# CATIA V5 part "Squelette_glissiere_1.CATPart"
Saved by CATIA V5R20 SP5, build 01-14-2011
Part number: Squelette_glissiere
Publications: "Longueur_int_coulisseau_1", "Longueur_ext_coulisseau_1", "Largeur_int_coulisseau_1", "Largeur_ext_coulisseau_1", "Distance_pivot_coulisseau", "épaisseur1_coulisseau_1", "épaisseur2_coulisseau_1", "Plan xy", "Plan yz", "Plan zx", "Point.1", "Point.2", "Point.3", "Point.4", "Droite.1", "Droite.2", "Droite.3", "Droite.4", "Point.11", "Point.12", "Point.13", "Point.14", "Droite.9", "Droite.10", "Droite.11", "Droite.12", "Point.15", "Droite.13", "Plan.1"
Bounding box of the stored display mesh (mm): x 0 to 74, y -4 to 15, z 0 to 20
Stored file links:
  C:\Users\MARLENE\Documents\IFMA\S3\IAO\Copie de CAO\Squelette_glissiere_1.CATPart
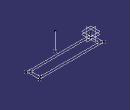
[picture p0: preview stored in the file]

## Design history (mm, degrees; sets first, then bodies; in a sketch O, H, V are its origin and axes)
Parameters
  Longueur_int_glissiere_1 = 68 mm
  Longueur_ext_glissiere_1 = 74 mm
  Largeur_int_glissiere_1 = 10 mm
  Largeur_ext_glissiere_1 = 15 mm
  Distance_pivot_glissiere = -4 mm
  `épaisseur1_glissiere_1` = 2.5 mm
  `épaisseur2_glissiere_1` = 3 mm
Set1
  Point1: (0, 0, 0)
  Point2: (74 {= Longueur_ext_glissiere_1}, 0, 0)
  Point3: (74, 15 {= Largeur_ext_glissiere_1}, 0)
  Point4: (0, 15, 0)
  Line1: type PtPt, FirstPoint Point1, SecondPoint Point2
  Line2: type PtPt, FirstPoint Point1, SecondPoint Point4
  Line3: type PtPt, FirstPoint Point3, SecondPoint Point4
  Line4: type PtPt, FirstPoint Point2, SecondPoint Point3
  Point5: (3 {= `épaisseur2_glissiere_1`}, 2.5 {= `épaisseur1_glissiere_1`}, 0)
  Point6: (71 {= `épaisseur2_glissiere_1` +Longueur_int_glissiere_1}, 2.5 {= `épaisseur1_glissiere_1`}, 0)
  Point7: (3 {= `épaisseur2_glissiere_1`}, 12.5 {= `épaisseur1_glissiere_1` +Largeur_int_glissiere_1}, 0)
  Point8: (71 {= `épaisseur2_glissiere_1` +Longueur_int_glissiere_1}, 12.5 {= `épaisseur1_glissiere_1` +Largeur_int_glissiere_1}, 0)
  Line5: type PtPt, FirstPoint Point5, SecondPoint Point7
  Line6: type PtPt, FirstPoint Point7, SecondPoint Point8
  Line7: type PtPt, FirstPoint Point8, SecondPoint Point6
  Line8: type PtPt, FirstPoint Point6, SecondPoint Point5
  Point9: (37 {= Longueur_ext_glissiere_1 /2}, -4 {= Distance_pivot_glissiere}, 0)
  Line9: type PtDir, RefPoint Point9, Direction xy-plane, Start 0, End 20
  Plane1: type Offset, RefPlane xy-plane, Offset 3
Body1 (main body)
